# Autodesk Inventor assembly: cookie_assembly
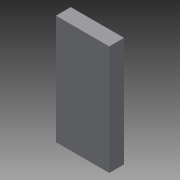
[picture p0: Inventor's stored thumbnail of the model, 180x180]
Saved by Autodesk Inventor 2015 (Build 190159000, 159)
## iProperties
Created: 2017-04
Part Number: cookie_assembly
Document SubType Name: Assembly
Designer: mcalderon
Author: mcalderon
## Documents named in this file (4)
- D:\2017-I\fabacademy\cookie_assembly.iam
- D:\2017-I\fabacademy\cubo.ipt
- D:\2017-I\fabacademy\cookie_blue.ipt
- D:\2017-I\fabacademy\cookie_green.ipt
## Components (3 placed, 3 different names)
1. cubo:1 — Rigid:1, Rigid:2
2. cookie_blue:1 — Rigid:1
3. cookie_green:1 — Rigid:2
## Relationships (2: WeldJoint 2)
- Rigid:1 [WeldJoint]: cubo:1 ↔ cookie_blue:1
- Rigid:2 [WeldJoint]: cubo:1 ↔ cookie_green:1
